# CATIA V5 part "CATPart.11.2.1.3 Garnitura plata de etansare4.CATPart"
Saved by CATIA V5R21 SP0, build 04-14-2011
Part number: Garnitura plata de etanşare.1.1.2
Bounding box of the stored display mesh (mm): x -4 to 4, y -3.804 to 3.804, z 0 to 2
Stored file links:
  C:\Users\MIRCEA\Desktop\MOM\Mogan\model\CATPart.11.2.1.3 Garnitura plata de etansare4.CATPart
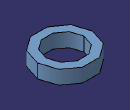
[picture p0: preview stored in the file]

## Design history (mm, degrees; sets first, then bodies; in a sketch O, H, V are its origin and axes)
Parameters
  Di = 5.5 mm
  De = 8 mm
  h = 2 mm
AxisSystem1: origin (0, 0, 0), X (1, 0, 0), Y (0, 1, 0), Z (0, 0, 1)
Body1 (main body)
  Sketch1 on xy-plane, origin (0, 0, 0), H (1, 0, 0), V (0, 1, 0)
    circle A1 centre (0, 0) radius 2.75
    circle A2 centre (0, 0) radius 4
    radius A1 = 2.75 {= Di/2}
    radius A2 = 4 {= De/2}
  Pad1: profile Sketch1, direction (0, 0, 1), length 2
